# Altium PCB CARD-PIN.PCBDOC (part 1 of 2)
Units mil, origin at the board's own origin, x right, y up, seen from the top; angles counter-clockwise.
Board outline 5110 x 4320 mil, 2 copper layers (Top Layer, Bottom Layer); 210 components, 32 nets, 795 pads, 360 vias.
Unrouted connection lines stored in the file: 450.
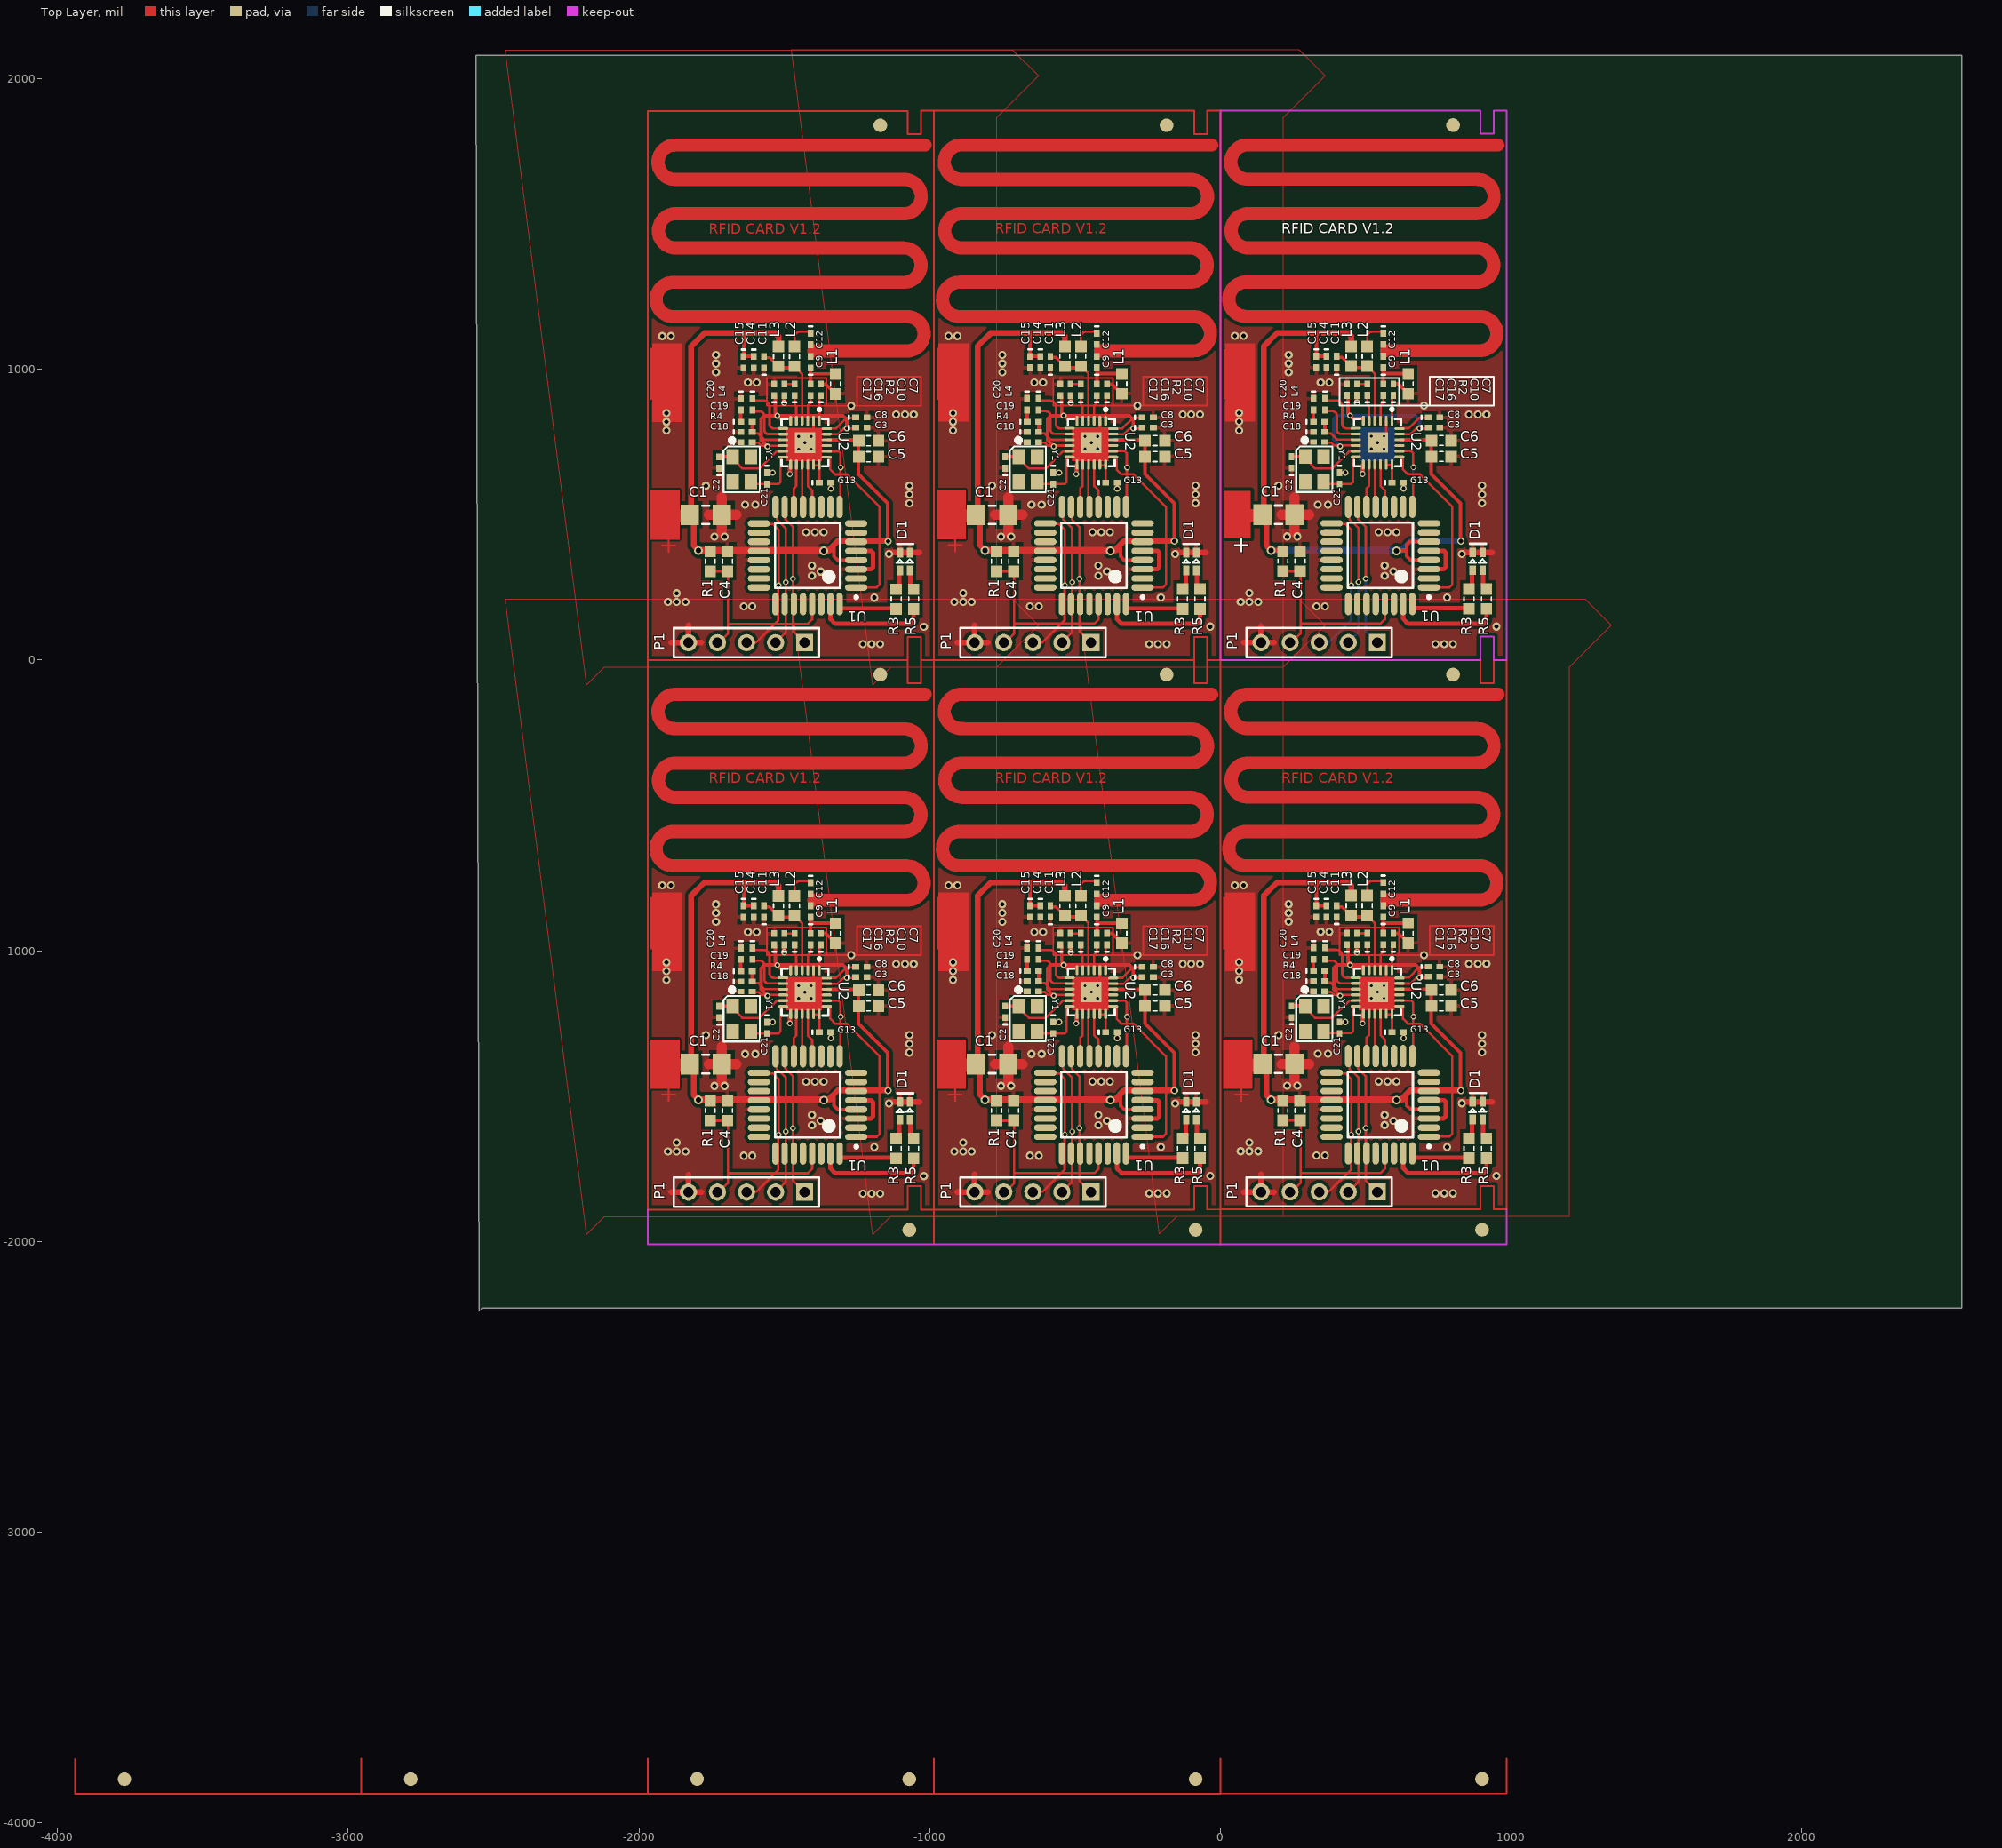
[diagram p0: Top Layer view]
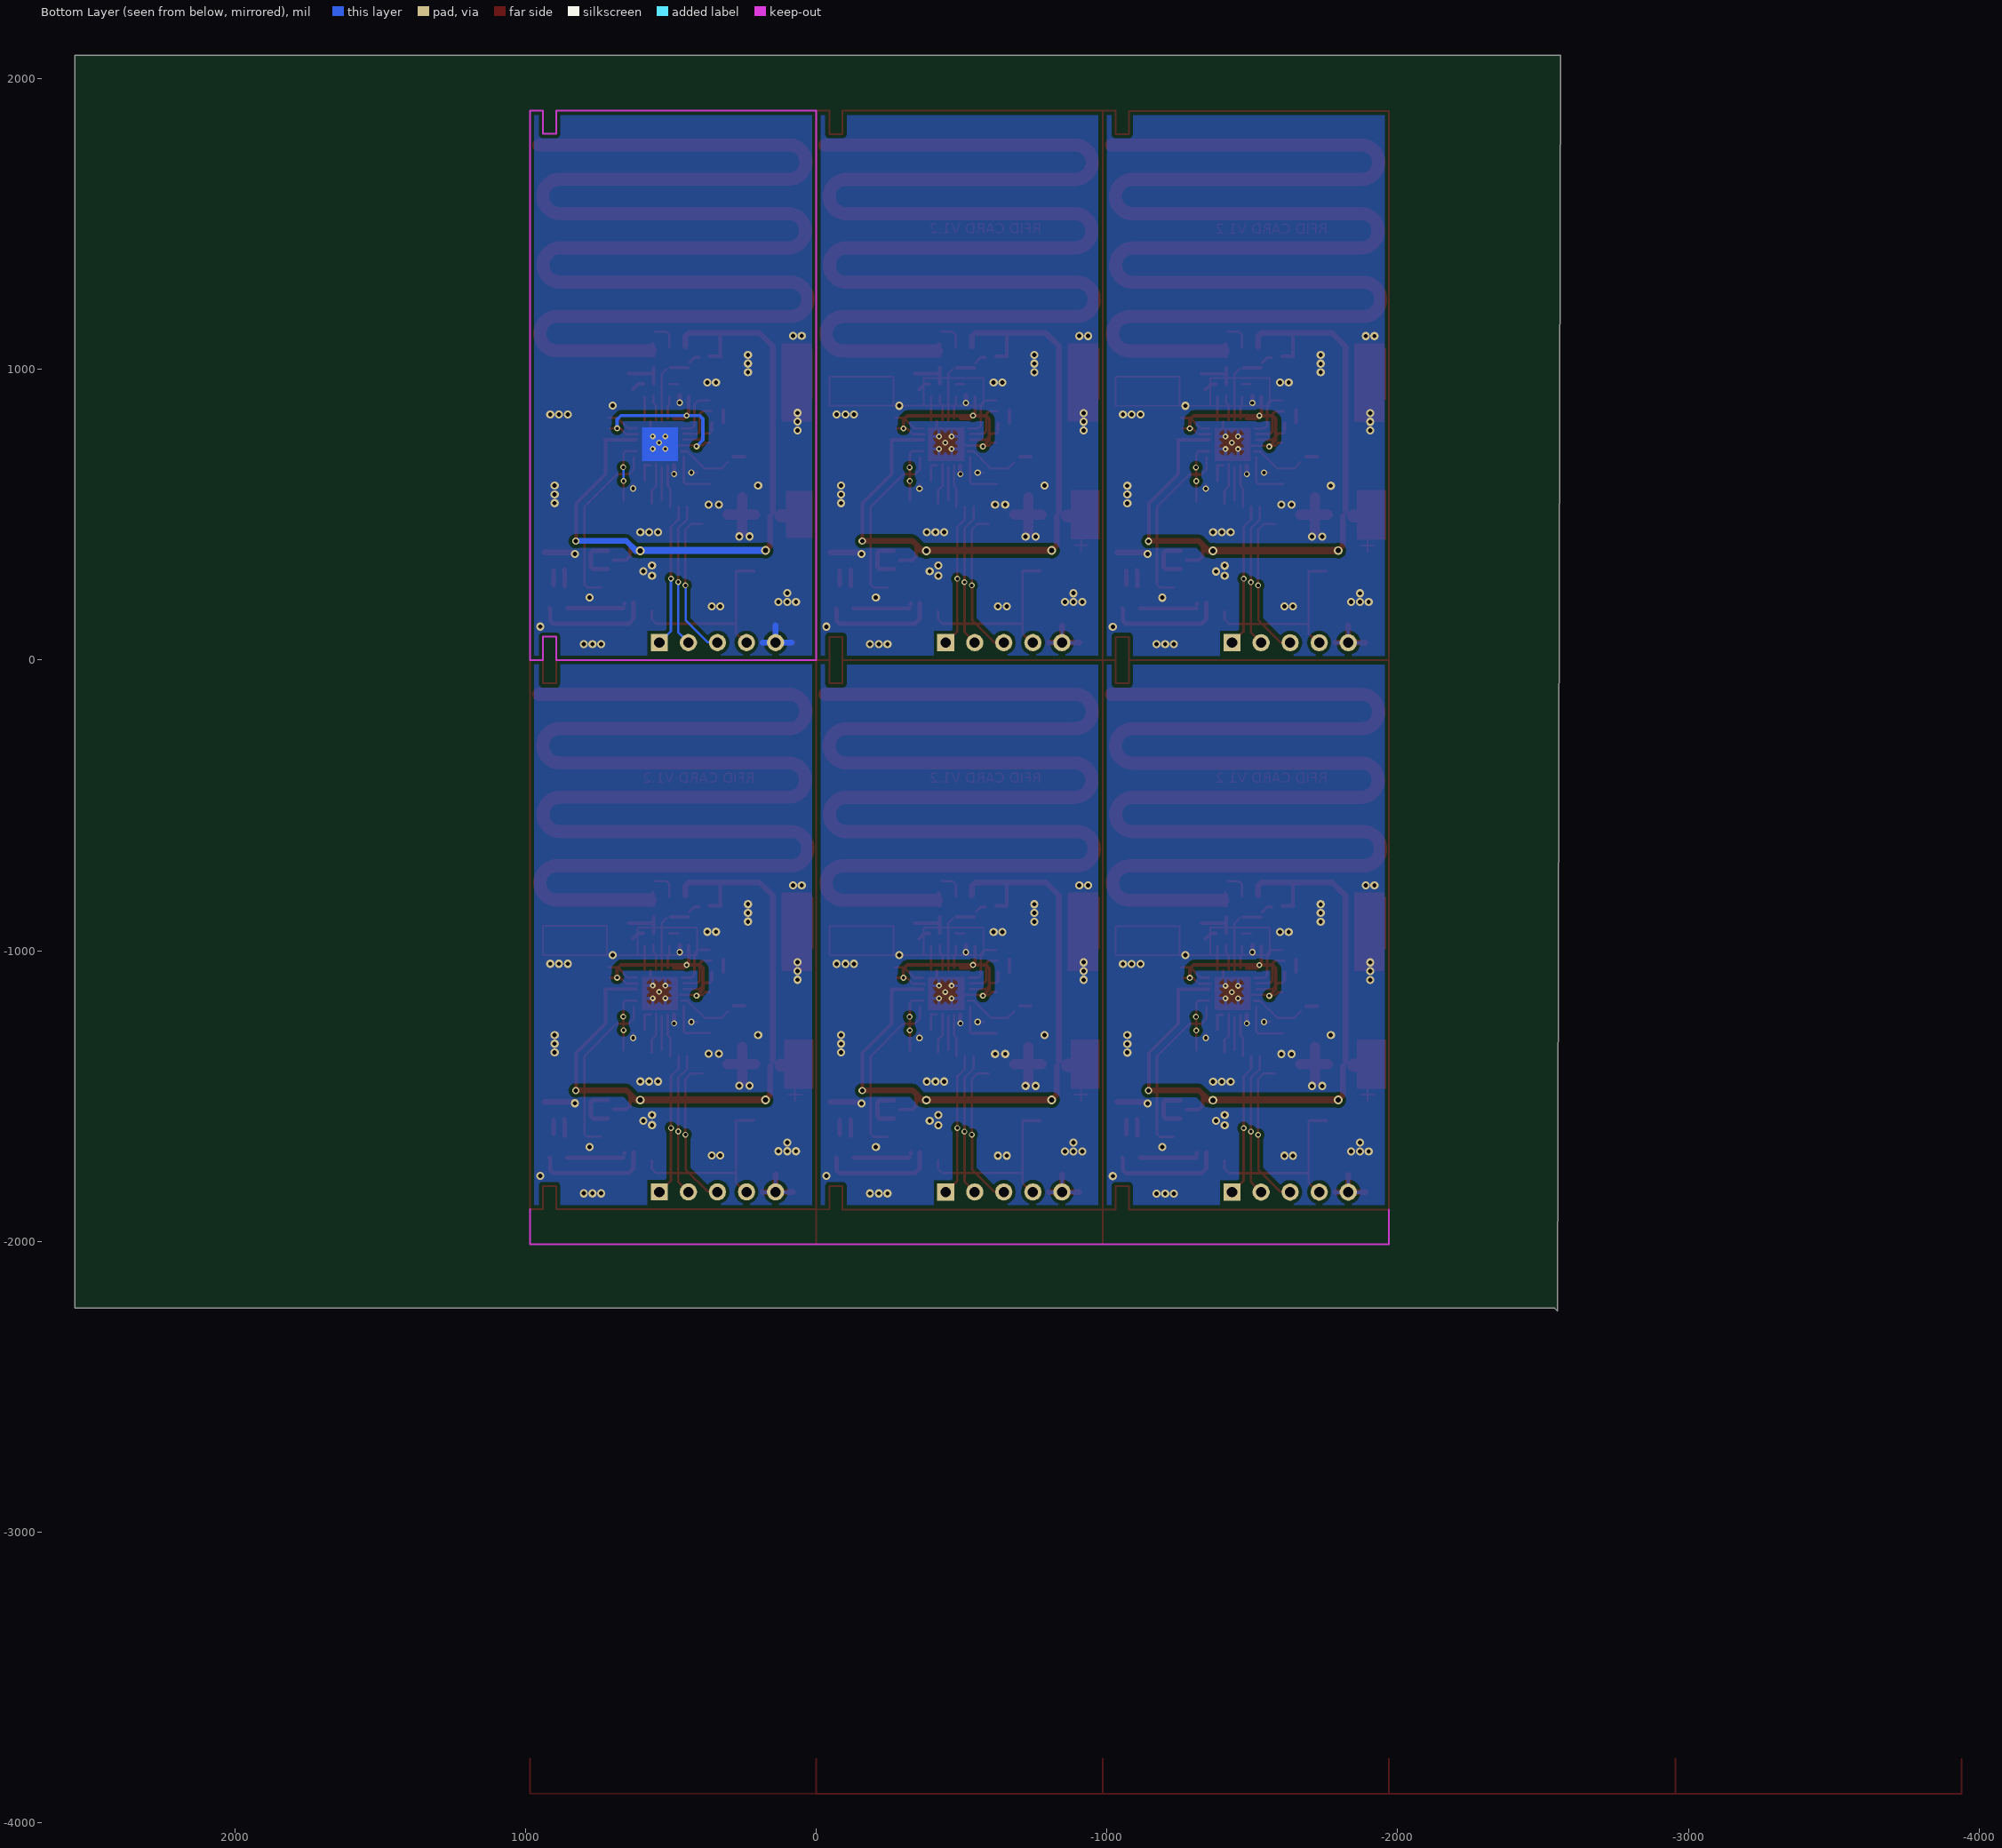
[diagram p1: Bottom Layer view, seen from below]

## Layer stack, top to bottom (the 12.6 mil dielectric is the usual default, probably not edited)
Top Layer: signal copper 1.4
Dielectric: core 12.6, FR-4, Dk 4.8
Bottom Layer: signal copper 1.4

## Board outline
-2560,2080 2550,2080 2550,-2230 -2540,-2230 -2550,-2240

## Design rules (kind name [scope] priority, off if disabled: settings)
Clearance [All] p1 off: gap=8
ComponentClearance [All] p1 off: gap=10 collisioncheckmode=3 verticalgap=10
DiffPairsRouting [All] p1 off: maxlimit=10 minlimit=10 mostfreqgap=10 maxuncoupledlength=500
HoleSize [All] p1: absolutevalues=TRUE maxlimit=100 minlimit=0 maxpercent=80.000 minpercent=20.000
PolygonConnect [All] p1: connectstyle=Relief reliefconductorwidth=12 reliefentries=4 polygonreliefangle="90 Angle"
RoutingVias [All] p1: holewidth=15 width=25 viastyle="Through Hole" minholewidth=8 minwidth=15 maxholewidth=80 maxwidth=50
SolderMaskExpansion [All] p1: expansion=4
TestPointUsage [All] p1: valid=0 allowmultiple=FALSE
Testpoint [All] p1: side=15 testpointundercomponent=TRUE minsize=40 maxsize=100 preferedsize=60 minholesize=0 maxholesize=40 preferedholesize=32 testpointgrid=1 style=1023 order=0-112345678
Width [All] p1: maxlimit=100 minlimit=8 preferedwidth=10 minimp=50.000000 maximp=50.000000 favimp=50.000000
16 further rules are at their usual default settings.

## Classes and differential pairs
component class card: C1 C2 C3 C4 C5 C6 C7 C8 C9 C10 C11 C12 C13 C14 C15 C16 C17 C18 C19 C20 C21 D1 D2 L1 L2 L3 L4 P1 P3 R1 R2 R3 R4 R5 U1 U2 Y1

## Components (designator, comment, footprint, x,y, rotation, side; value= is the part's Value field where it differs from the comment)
C1 "Cap" 3216[1206] 200,-1390 r180 top
C1 "Cap" 3216[1206] -785,-1390.24 r180 top
C1 "Cap" 3216[1206] -1770,-1390.47 r180 top
C1 "Cap" 3216[1206] -1770,499.53 r180 top
C1 "Cap" 3216[1206] -785,499.76 r180 top
C1 "Cap" 3216[1206] 200,500 r180 top
C2 "Cap" 0402-A 245,-1210 r90 top
C2 "Cap" 0402-A -740,-1210.24 r90 top
C2 "Cap" 0402-A -1725,-1210.47 r90 top
C2 "Cap" 0402-A -1725,679.53 r90 top
C2 "Cap" 0402-A -740,679.76 r90 top
C2 "Cap" 0402-A 245,680 r90 top
C3 "Cap" 0402-A 735,-1090 r0 top
C3 "Cap" 0402-A -250,-1090.24 r0 top
C3 "Cap" 0402-A -1235,-1090.47 r0 top
C3 "Cap" 0402-A -1235,799.53 r0 top
C3 "Cap" 0402-A -250,799.76 r0 top
C3 "Cap" 0402-A 735,800 r0 top
C4 "Cap" 0603 274,-1550 r90 top
C4 "Cap" 0603 -711,-1550.24 r90 top
C4 "Cap" 0603 -1696,-1550.47 r90 top
C4 "Cap" 0603 -1696,339.53 r90 top
C4 "Cap" 0603 -711,339.76 r90 top
C4 "Cap" 0603 274,340 r90 top
C5 "Cap" 0603 760,-1190 r0 top
C5 "Cap" 0603 -225,-1190.24 r0 top
C5 "Cap" 0603 -1210,-1190.47 r0 top
C5 "Cap" 0603 -1210,699.53 r0 top
C5 "Cap" 0603 -225,699.76 r0 top
C5 "Cap" 0603 760,700 r0 top
C6 "Cap" 0603 760,-1135 r0 top
C6 "Cap" 0603 -225,-1135.24 r0 top
C6 "Cap" 0603 -1210,-1135.47 r0 top
C6 "Cap" 0603 -1210,754.53 r0 top
C6 "Cap" 0603 -225,754.76 r0 top
C6 "Cap" 0603 760,755 r0 top
C7 "Cap" 0402-A 595,-960 r90 top
C7 "Cap" 0402-A -390,-960.24 r90 top
C7 "Cap" 0402-A -1375,-960.47 r90 top
C7 "Cap" 0402-A -1375,929.53 r90 top
C7 "Cap" 0402-A -390,929.76 r90 top
C7 "Cap" 0402-A 595,930 r90 top
C8 "Cap" 0402-A 735,-1055 r0 top
C8 "Cap" 0402-A -250,-1055.24 r0 top
C8 "Cap" 0402-A -1235,-1055.47 r0 top
C8 "Cap" 0402-A -1235,834.53 r0 top
C8 "Cap" 0402-A -250,834.76 r0 top
C8 "Cap" 0402-A 735,835 r0 top
C9 "Cap" 0402-A 560,-865 r90 top
C9 "Cap" 0402-A -425,-865.24 r90 top
C9 "Cap" 0402-A -1410,-865.47 r90 top
C9 "Cap" 0402-A -1410,1024.53 r90 top
C9 "Cap" 0402-A -425,1024.76 r90 top
C9 "Cap" 0402-A 560,1025 r90 top
C10 "Cap" 0402-A 560,-960 r90 top
C10 "Cap" 0402-A -425,-960.24 r90 top
C10 "Cap" 0402-A -1410,-960.47 r90 top
C10 "Cap" 0402-A -1410,929.53 r90 top
C10 "Cap" 0402-A -425,929.76 r90 top
C10 "Cap" 0402-A 560,930 r90 top
C11 "Cap" 0402-A 400,-865 r90 top
C11 "Cap" 0402-A -585,-865.24 r90 top
C11 "Cap" 0402-A -1570,-865.47 r90 top
C11 "Cap" 0402-A -1570,1024.53 r90 top
C11 "Cap" 0402-A -585,1024.76 r90 top
C11 "Cap" 0402-A 400,1025 r90 top
C12 "Cap" 0402-A 560,-785 r270 top
C12 "Cap" 0402-A -425,-785.24 r270 top
C12 "Cap" 0402-A -1410,-785.47 r270 top
C12 "Cap" 0402-A -1410,1104.53 r270 top
C12 "Cap" 0402-A -425,1104.76 r270 top
C12 "Cap" 0402-A 560,1105 r270 top
C13 "Cap" 0402-A 610,-1280 r0 top
C13 "Cap" 0402-A -375,-1280.24 r0 top
C13 "Cap" 0402-A -1360,-1280.47 r0 top
C13 "Cap" 0402-A -1360,609.53 r0 top
C13 "Cap" 0402-A -375,609.76 r0 top
C13 "Cap" 0402-A 610,610 r0 top
C14 "Cap" 0402-A 365,-865 r270 top
C14 "Cap" 0402-A -620,-865.24 r270 top
C14 "Cap" 0402-A -1605,-865.47 r270 top
C14 "Cap" 0402-A -1605,1024.53 r270 top
C14 "Cap" 0402-A -620,1024.76 r270 top
C14 "Cap" 0402-A 365,1025 r270 top
C15 "Cap" 0402-A 330,-865 r270 top
C15 "Cap" 0402-A -655,-865.24 r270 top
C15 "Cap" 0402-A -1640,-865.47 r270 top
C15 "Cap" 0402-A -1640,1024.53 r270 top
C15 "Cap" 0402-A -655,1024.76 r270 top
C15 "Cap" 0402-A 330,1025 r270 top
C16 "Cap" 0402-A 470,-960 r90 top
C16 "Cap" 0402-A -515,-960.24 r90 top
C16 "Cap" 0402-A -1500,-960.47 r90 top
C16 "Cap" 0402-A -1500,929.53 r90 top
C16 "Cap" 0402-A -515,929.76 r90 top
C16 "Cap" 0402-A 470,930 r90 top
C17 "Cap" 0402-A 435,-960 r90 top
C17 "Cap" 0402-A -550,-960.24 r90 top
C17 "Cap" 0402-A -1535,-960.47 r90 top
C17 "Cap" 0402-A -1535,929.53 r90 top
C17 "Cap" 0402-A -550,929.76 r90 top
C17 "Cap" 0402-A 435,930 r90 top
C18 "Cap" 0402-A 340,-1140 r0 top
C18 "Cap" 0402-A -645,-1140.24 r0 top
C18 "Cap" 0402-A -1630,-1140.47 r0 top
C18 "Cap" 0402-A -1630,749.53 r0 top
C18 "Cap" 0402-A -645,749.76 r0 top
C18 "Cap" 0402-A 340,750 r0 top
C19 "Cap" 0402-A 340,-1105 r0 top
C19 "Cap" 0402-A -645,-1105.24 r0 top
C19 "Cap" 0402-A -1630,-1105.47 r0 top
C19 "Cap" 0402-A -1630,784.53 r0 top
C19 "Cap" 0402-A -645,784.76 r0 top
C19 "Cap" 0402-A 340,785 r0 top
C20 "Cap" 0402-A 320,-1010 r270 top
C20 "Cap" 0402-A -665,-1010.24 r270 top
C20 "Cap" 0402-A -1650,-1010.47 r270 top
C20 "Cap" 0402-A -1650,879.53 r270 top
C20 "Cap" 0402-A -665,879.76 r270 top
C20 "Cap" 0402-A 320,880 r270 top
C21 "Cap" 0402-A 410,-1265 r270 top
C21 "Cap" 0402-A -575,-1265.24 r270 top
C21 "Cap" 0402-A -1560,-1265.47 r270 top
C21 "Cap" 0402-A -1560,624.53 r270 top
C21 "Cap" 0402-A -575,624.76 r270 top
C21 "Cap" 0402-A 410,625 r270 top
D1 "LED" 0603-LED-DOUBLE 902,-1580 r90 top
D1 "LED" 0603-LED-DOUBLE -83,-1580.24 r90 top
D1 "LED" 0603-LED-DOUBLE -1068,-1580.47 r90 top
D1 "LED" 0603-LED-DOUBLE -1068,309.53 r90 top
D1 "LED" 0603-LED-DOUBLE -83,309.76 r90 top
D1 "LED" 0603-LED-DOUBLE 902,310 r90 top
L1 "Inductor" 0603 646,-940 r270 top
L1 "Inductor" 0603 -339,-940.24 r270 top
L1 "Inductor" 0603 -1324,-940.47 r270 top
L1 "Inductor" 0603 -1324,949.53 r270 top
L1 "Inductor" 0603 -339,949.76 r270 top
L1 "Inductor" 0603 646,950 r270 top
L2 "Inductor" 0603 505,-845 r90 top
L2 "Inductor" 0603 -480,-845.24 r90 top
L2 "Inductor" 0603 -1465,-845.47 r90 top
L2 "Inductor" 0603 -1465,1044.53 r90 top
L2 "Inductor" 0603 -480,1044.76 r90 top
L2 "Inductor" 0603 505,1045 r90 top
L3 "Inductor" 0603 450,-845 r90 top
L3 "Inductor" 0603 -535,-845.24 r90 top
L3 "Inductor" 0603 -1520,-845.47 r90 top
L3 "Inductor" 0603 -1520,1044.53 r90 top
L3 "Inductor" 0603 -535,1044.76 r90 top
L3 "Inductor" 0603 450,1045 r90 top
L4 "Inductor" 0402-A 360,-1010 r270 top
L4 "Inductor" 0402-A -625,-1010.24 r270 top
L4 "Inductor" 0402-A -1610,-1010.47 r270 top
L4 "Inductor" 0402-A -1610,879.53 r270 top
L4 "Inductor" 0402-A -625,879.76 r270 top
L4 "Inductor" 0402-A 360,880 r270 top
P1 "ISP" HDR1X5 540,-1830 r180 top
P1 "ISP" HDR1X5 -445,-1830.24 r180 top
P1 "ISP" HDR1X5 -1430,-1830.47 r180 top
P1 "ISP" HDR1X5 -1430,59.53 r180 top
P1 "ISP" HDR1X5 -445,59.76 r180 top
P1 "ISP" HDR1X5 540,60 r180 top
R1 "Res1" 0603 215,-1550 r90 top
R1 "Res1" 0603 -770,-1550.24 r90 top
R1 "Res1" 0603 -1755,-1550.47 r90 top
R1 "Res1" 0603 -1755,339.53 r90 top
R1 "Res1" 0603 -770,339.76 r90 top
R1 "Res1" 0603 215,340 r90 top
R2 "Res1" 0402-A 505,-960 r90 top
R2 "Res1" 0402-A -480,-960.24 r90 top
R2 "Res1" 0402-A -1465,-960.47 r90 top
R2 "Res1" 0402-A -1465,929.53 r90 top
R2 "Res1" 0402-A -480,929.76 r90 top
R2 "Res1" 0402-A 505,930 r90 top
R3 "Res1" 0603 855,-1680 r90 top
R3 "Res1" 0603 -130,-1680.24 r90 top
R3 "Res1" 0603 -1115,-1680.47 r90 top
R3 "Res1" 0603 -1115,209.53 r90 top
R3 "Res1" 0603 -130,209.76 r90 top
R3 "Res1" 0603 855,210 r90 top
R4 "Res1" 0402-A 340,-1070 r0 top
R4 "Res1" 0402-A -645,-1070.24 r0 top
R4 "Res1" 0402-A -1630,-1070.47 r0 top
R4 "Res1" 0402-A -1630,819.53 r0 top
R4 "Res1" 0402-A -645,819.76 r0 top
R4 "Res1" 0402-A 340,820 r0 top
R5 "Res1" 0603 915,-1680 r90 top
R5 "Res1" 0603 -70,-1680.24 r90 top
R5 "Res1" 0603 -1055,-1680.47 r90 top
R5 "Res1" 0603 -1055,209.53 r90 top
R5 "Res1" 0603 -70,209.76 r90 top
R5 "Res1" 0603 915,210 r90 top
U1 "ATmega8-16AC" 32A_M 550,-1530 r180 top
U1 "ATmega8-16AC" 32A_M -435,-1530.24 r180 top
U1 "ATmega8-16AC" 32A_M -1420,-1530.47 r180 top
U1 "ATmega8-16AC" 32A_M -1420,359.53 r180 top
U1 "ATmega8-16AC" 32A_M -435,359.76 r180 top
U1 "ATmega8-16AC" 32A_M 550,360 r180 top
U2 "A7139" QFN24N 541,-1142 r270 top
U2 "A7139" QFN24N -444,-1142.24 r270 top
U2 "A7139" QFN24N -1429,-1142.47 r270 top
U2 "A7139" QFN24N -1429,747.53 r270 top
U2 "A7139" QFN24N -444,747.76 r270 top
U2 "A7139" QFN24N 541,748 r270 top
Y1 "12.8M CL=20pF" XT3225 355,-1190 r270 top
Y1 "12.8M CL=20pF" XT3225 -630,-1190.24 r270 top
Y1 "12.8M CL=20pF" XT3225 -1615,-1190.47 r270 top
Y1 "12.8M CL=20pF" XT3225 -1615,699.53 r270 top
Y1 "12.8M CL=20pF" XT3225 -630,699.76 r270 top
Y1 "12.8M CL=20pF" XT3225 355,700 r270 top

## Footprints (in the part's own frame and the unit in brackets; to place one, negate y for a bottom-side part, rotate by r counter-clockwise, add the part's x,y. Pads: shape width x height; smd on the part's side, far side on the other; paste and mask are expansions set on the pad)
32A_M [mm] "32-Pin Thin Quad Flat Pack 0.8 mm Pitch, IPC Low Density"
  oval 1.95x0.559 smd: 1(-4.25,2.8) 2(-4.25,2) 3(-4.25,1.2) 4(-4.25,0.4) 5(-4.25,-0.4) 6(-4.25,-1.2) 7(-4.25,-2) 8(-4.25,-2.8) 17(4.25,-2.8) 18(4.25,-2) 19(4.25,-1.2) 20(4.25,-0.4) 21(4.25,0.4) 22(4.25,1.2) 23(4.25,2) 24(4.25,2.8)
  oval 0.559x1.95 smd: 9(-2.8,-4.25) 10(-2,-4.25) 11(-1.2,-4.25) 12(-0.4,-4.25) 13(0.4,-4.25) 14(1.2,-4.25) 15(2,-4.25) 16(2.8,-4.25) 25(2.8,4.25) 26(2,4.25) 27(1.2,4.25) 28(0.4,4.25) 29(-0.4,4.25) 30(-1.2,4.25) 31(-2,4.25) 32(-2.8,4.25)
  silkscreen extent -4.38,-2.85 2.85,3.77, body extent -3.5,-3.5 3.5,3.5, height 1.2
0402-A [mm] "Chip Inductor; Body 1 x 0.5 mm (LxW typ)"
  rect 0.6x0.5 smd: 1(-0.5,0) 2(0.5,0)
  silkscreen extent -1.1,-0.15 -1.1,0.15
0603 [mm]
  rect 1x1 smd: 1(-0.864,0) 2(0.864,0)
  silkscreen extent -0.18,-0.43 0.18,0.43
0603-LED-DOUBLE [mil]
  rect 33x22 smd: 1(-1,34) 2(-1,0) 3(60,34) 4(60,0)
  silkscreen extent 24,-12 90,47
3216[1206] [mm] "Chip Resistor; Body 3.2 x 1.6 mm (LxW typ)"
  rect 1.6x1.8 smd: 1(-1.4,0) 2(1.4,0)
  silkscreen extent -0.3,-0.8 0.3,0.8
HDR1X5 [mm] "Connector; Header; 5 Position"
  rect 1.5x1.5 hole 0.9: 1(0,0)
  round 1.5 hole 0.9: 2(2.54,0) 3(5.08,0) 4(7.62,0) 5(10.16,0)
  silkscreen extent -1.27,-1.27 11.43,1.27
QFN24N [mm] "QFN, 24-Leads, Body 4.1x4.1mm (max), Pitch 0.50mm, IPC Medium Density"
  oval 0.889x0.25 smd: 1(-1.905,1.25) 2(-1.905,0.75) 3(-1.905,0.25) 4(-1.905,-0.25) 5(-1.905,-0.75) 6(-1.905,-1.25) 13(1.905,-1.25) 14(1.905,-0.75) 15(1.905,-0.25) 16(1.905,0.25) 17(1.905,0.75) 18(1.905,1.25)
  oval 0.25x0.889 smd: 7(-1.25,-1.905) 8(-0.75,-1.905) 9(-0.25,-1.905) 10(0.25,-1.905) 11(0.75,-1.905) 12(1.25,-1.905) 19(1.25,1.905) 20(0.75,1.905) 21(0.25,1.905) 22(-0.25,1.905) 23(-0.75,1.905) 24(-1.219,1.905)
  rect 1.8x1.8 smd: 25(0,0)
  silkscreen extent -3.02,-2.05 2.05,2.05, body extent -2.05,-2.05 2.05,2.05, height 0.8
XT3225 [mm]
  rect 1.3x1.1 smd: 1(0,-1.6) 2(2.2,-1.6) 3(2.2,0) 4(0,0)
  silkscreen extent -1.6,-2.39 3.1,0.76

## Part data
C1 C1 C1 C1 C1 C1 C2 C2 C2 C2 C2 C2 C3 C3 C3 C3 C3 C3 C4 C4 C4 C4 C4 C4 C5 C5 C5 C5 C5 C5 C6 C6 C6 C6 C6 C6 C7 C7 C7 C7 C7 C7 C8 C8 C8 C8 C8 C8 C9 C9 C9 C9 C9 C9 C10 C10 C10 C10 C10 C10 C11 C11 C11 C11 C11 C11 C12 C12 C12 C12 C12 C12 C13 C13 C13 C13 C13 C13 C14 C14 C14 C14 C14 C14 C15 C15 C15 C15 C15 C15 C16 C16 C16 C16 C16 C16 C17 C17 C17 C17 C17 C17 C18 C18 C18 C18 C18 C18 C19 C19 C19 C19 C19 C19 C20 C20 C20 C20 C20 C20 C21 C21 C21 C21 C21 C21: "Capacitor"
D1 D1 D1 D1 D1 D1: library part LED-DOUBLE
P1 P1 P1 P1 P1 P1: library part "Header 5", "Header, 5-Pin"
R1 R1 R1 R1 R1 R1 R2 R2 R2 R2 R2 R2 R3 R3 R3 R3 R3 R3 R4 R4 R4 R4 R4 R4 R5 R5 R5 R5 R5 R5: "Resistor"
U1 U1 U1 U1 U1 U1: "8-Bit AVR Microcontroller with 8K Bytes of In-System Programmable Flash Memory"
Y1 Y1 Y1 Y1 Y1 Y1: library part XTAL, "Crystal Oscillator"

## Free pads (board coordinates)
  round 47.24 smd: 3(-1170,-50.47) 3(-1170,1839.53) 3(-185,-50.24) 3(-185,1839.76) 3(800,-50) 3(800,1840) 6(-1070,-3850.47) 6(-1070,-1960.47) 6(-85,-3850.24) 6(-85,-1960.24) 6(900,-3850) 6(900,-1960) 7(-3770,-3850.47) 7(-2785,-3850.24) 7(-1800,-3850)

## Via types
v1: diameter 28, hole 15, Top Layer to Bottom Layer, 240 vias
v2: diameter 20, hole 12, Top Layer to Bottom Layer, 36 vias
v3: diameter 20, hole 10, Top Layer to Bottom Layer, tented top, 30 vias
v4: diameter 22, hole 13, Top Layer to Bottom Layer, 18 vias
v5: diameter 21, hole 11, Top Layer to Bottom Layer, 18 vias
v6: diameter 30, hole 18, Top Layer to Bottom Layer, 12 vias
v7: diameter 25, hole 15, Top Layer to Bottom Layer, 6 vias

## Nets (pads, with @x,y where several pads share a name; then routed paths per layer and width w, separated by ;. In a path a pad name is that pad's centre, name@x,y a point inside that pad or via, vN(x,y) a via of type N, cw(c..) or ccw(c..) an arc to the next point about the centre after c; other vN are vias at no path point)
GIO1: U1.1 U2.19 | length 3555.5
  Top Layer w8: U2.19@-1342,-1193.47 -1342,-1234.47 -1325,-1251.47 -1284,-1251.47 -1172,-1363.47 -1172,-1630.47 -1182,-1640.47 U1.1@-1229,-1640.47 ; U2.19@-1342,696.53 -1342,655.53 -1325,638.53 -1284,638.53 -1172,526.53 -1172,259.53 -1182,249.53 U1.1@-1229,249.53 ; U2.19@-357,-1193.24 -357,-1234.24 -340,-1251.24 -299,-1251.24 -187,-1363.24 -187,-1630.24 -197,-1640.24 U1.1@-244,-1640.24 ; U2.19@-357,696.76 -357,655.76 -340,638.76 -299,638.76 -187,526.76 -187,259.76 -197,249.76 U1.1@-244,249.76 ; U2.19@628,-1193 628,-1234 645,-1251 686,-1251 798,-1363 798,-1630 788,-1640 U1.1@741,-1640 ; U2.19@628,697 628,656 645,639 686,639 798,527 798,260 788,250 U1.1@741,250
GIO2: U1.9 U2.20 | length 1283.3
  Top Layer w8: U2.20@-1351.44,-1172 -1313.47,-1172 -1307,-1178.47 v2@-1307,-1228.47 ; U2.20@-1351.44,718 -1313.47,718 -1307,711.53 v2@-1307,661.53 ; U1.9@-1307,-1343.24 v2(-1307,-1274.47) ; v2@-1307,-1271.47 v2@-1307,-1223.47 ; U1.9@-1307,546.76 v2(-1307,615.53) ; v2@-1307,618.53 v2@-1307,666.53 ; U2.20@-366.44,-1171.76 -328.47,-1171.76 -322,-1178.24 v2@-322,-1228.24 ; U2.20@-366.44,718.24 -328.47,718.24 -322,711.76 v2@-322,661.76 ; U1.9@-322,-1343 v2(-322,-1274.24) ; v2@-322,-1271.24 v2@-322,-1223.24 ; U1.9@-322,547 v2(-322,615.76) ; v2@-322,618.76 v2@-322,666.76 ; U2.20@618.56,-1171.53 656.53,-1171.53 663,-1178 v2@663,-1228 ; U2.20@618.56,718.47 656.53,718.47 663,712 v2@663,662 ; U1.9@663,-1342.76 v2(663,-1274) ; v2@663,-1271 v2@663,-1223 ; U1.9@663,547.24 v2(663,616)
  Bottom Layer w8: v2@663,619 v2@663,667
  other v2: -1306,-1227.47 -321,-1227.24 664,-1227 -1306,662.53 -321,662.76 664,663
GND: C1.1 C2.1 C3.2 C4.2 C5.2 C6.2 C7.2 C8.2 C11.1 C13.2 C14.2 C15.2 C16.1 C17.2 C18.1 C19.1 C20.1 C21.1 D1.3 D1.4 L1.2 P1.5 U1.3 U1.5 U1.21 U2.2 U2.13 U2.25 | length 5774.5
  Top Layer w10: v4@-1550,-1245.47 v4@-1541,-1245.47 ; v4@-1550,644.53 v4@-1541,644.53 ; U2.25@-1399.47,-1112.94 U2.2@-1399.47,-1069.47 ; U2.25@-1399.47,777.06 U2.2@-1399.47,820.53 ; v4@-1340,-1299.61 C13.2@-1340,-1285.47 ; v4@-1340,590.39 C13.2@-1340,604.53 ; v4@-565,-1245.24 v4@-556,-1245.24 ; v4@-565,644.76 v4@-556,644.76 ; U2.25@-414.47,-1112.71 U2.2@-414.47,-1069.24 ; U2.25@-414.47,777.29 U2.2@-414.47,820.76 ; v4@-355,-1299.38 C13.2@-355,-1285.24 ; v4@-355,590.62 C13.2@-355,604.76 ; v4@420,-1245 v4@429,-1245 ; v4@420,645 v4@429,645 ; U2.25@570.53,-1112.47 U2.2@570.53,-1069 ; U2.25@570.53,777.53 U2.2@570.53,821 ; v4@630,-1299.14 C13.2@630,-1285 ; v4@630,590.86 C13.2@630,605
  Top Layer w12: C7.2@-1375,-940.79 -1357.69,-940.79 L1.2@-1339,-959.47 ; C7.2@-1375,949.21 -1357.69,949.21 L1.2@-1339,930.53 ; C7.2@-390,-940.55 -372.69,-940.55 L1.2@-354,-959.24 ; C7.2@-390,949.45 -372.69,949.45 L1.2@-354,930.76 ; C7.2@595,-940.31 612.31,-940.31 L1.2@631,-959 ; C7.2@595,949.69 612.31,949.69 L1.2@631,931
  Top Layer w15: v4@-1500,-1006.47 C16.1@-1500,-980.16 ; v4@-1500,883.53 C16.1@-1500,909.84 ; v2@-1480,-1250.47 U2.13@-1480,-1220.47 ; v2@-1480,639.53 U2.13@-1480,669.53 ; U1.3@-1252.68,-1577.72 -1202.24,-1577.72 -1195,-1570.47 -1195,-1520.47 -1200.75,-1514.72 U1.5@-1252.68,-1514.72 ; U1.3@-1252.68,312.28 -1202.24,312.28 -1195,319.53 -1195,369.53 -1200.75,375.28 U1.5@-1252.68,375.28 ; v4@-515,-1006.24 C16.1@-515,-979.92 ; v4@-515,883.76 C16.1@-515,910.08 ; v2@-495,-1250.24 U2.13@-495,-1220.24 ; v2@-495,639.76 U2.13@-495,669.76 ; U1.3@-267.68,-1577.48 -217.24,-1577.48 -210,-1570.24 -210,-1520.24 -215.75,-1514.49 U1.5@-267.68,-1514.49 ; U1.3@-267.68,312.52 -217.24,312.52 -210,319.76 -210,369.76 -215.75,375.51 U1.5@-267.68,375.51 ; v4@470,-1006 C16.1@470,-979.68 ; v4@470,884 C16.1@470,910.32 ; v2@490,-1250 U2.13@490,-1220 ; v2@490,640 U2.13@490,670 ; U1.3@717.32,-1577.24 767.76,-1577.24 775,-1570 775,-1520 769.25,-1514.25 U1.5@717.32,-1514.25 ; U1.3@717.32,312.76 767.76,312.76 775,320 775,370 769.25,375.75 U1.5@717.32,375.75
  Top Layer w20: -1890,-1830.47 -1785,-1830.47 -1885,-1830.47 ; -1890,59.53 -1785,59.53 -1885,59.53 ; P1.5@-1830,-1830.47 -1830,-1775.47 ; P1.5@-1830,-1825.47 -1830,-1770.47 ; P1.5@-1830,59.53 -1830,114.53 ; P1.5@-1830,64.53 -1830,119.53 ; v1@-1130,-1520.47 -1035,-1520.47 ; v1@-1130,369.53 -1035,369.53 ; -905,-1830.24 -800,-1830.24 -900,-1830.24 ; -905,59.76 -800,59.76 -900,59.76 ; P1.5@-845,-1830.24 -845,-1775.24 ; P1.5@-845,-1825.24 -845,-1770.24 ; P1.5@-845,59.76 -845,114.76 ; P1.5@-845,64.76 -845,119.76 ; v1@-145,-1520.24 -50,-1520.24 ; v1@-145,369.76 -50,369.76 ; 80,-1830 185,-1830 85,-1830 ; 80,60 185,60 ; P1.5@140,-1830 140,-1775 ; P1.5@140,-1825 140,-1770 ; P1.5@140,60 140,115 ; v1@840,-1520 935,-1520 ; v1@840,370 935,370
  Top Layer w35: -1760,-1390.47 -1665,-1390.47 ; -1760,499.53 -1665,499.53 ; -1715,-1450.47 -1715,-1330.47 ; -1715,439.53 -1715,559.53 ; -775,-1390.24 -680,-1390.24 ; -775,499.76 -680,499.76 ; -730,-1450.24 -730,-1330.24 ; -730,439.76 -730,559.76 ; 210,-1390 305,-1390 ; 210,500 305,500 ; 255,-1450 255,-1330 ; 255,440 255,560
  Bottom Layer w20: 85,60 185,60 ; P1.5@140,65 140,120
  other v1: -1230,-1835.47 -1200,-1835.47 -1170,-1835.47 -245,-1835.24 -215,-1835.24 -185,-1835.24 740,-1835 770,-1835 800,-1835 -1020,-1775.47 -35,-1775.24 950,-1775 -1640,-1705.47 -1610,-1705.47 -655,-1705.24 -625,-1705.24 330,-1705 360,-1705 -1900,-1690.47 -1870,-1690.47 -1840,-1690.47 -915,-1690.24 -885,-1690.24 -855,-1690.24 70,-1690 100,-1690 130,-1690 -1190,-1675.47 -205,-1675.24 780,-1675 -1870,-1660.47 -885,-1660.24 100,-1660 -1405,-1600.47 -420,-1600.24 565,-1600 -1375,-1585.47 -390,-1585.24 595,-1585 -1405,-1565.47 -420,-1565.24 565,-1565 -1140,-1525.47 -155,-1525.24 830,-1525 -1740,-1465.47 -1705,-1465.47 -755,-1465.24 -720,-1465.24 230,-1465 265,-1465 -1425,-1450.47 -1395,-1450.47 -1365,-1450.47 -440,-1450.24 -410,-1450.24 -380,-1450.24 545,-1450 575,-1450 605,-1450 -1635,-1355.47 -1600,-1355.47 -650,-1355.24 -615,-1355.24 335,-1355 370,-1355 -1070,-1350.47 -85,-1350.24 900,-1350 -1070,-1320.47 -85,-1320.24 900,-1320 -1770,-1290.47 -1070,-1290.47 -785,-1290.24 -85,-1290.24 200,-1290 900,-1290 -1905,-1100.47 -920,-1100.24 65,-1100 -1905,-1070.47 -920,-1070.24 65,-1070 -1115,-1045.47 -1085,-1045.47 -1055,-1045.47 -130,-1045.24 -100,-1045.24 -70,-1045.24 855,-1045 885,-1045 915,-1045 -1905,-1040.47 -920,-1040.24 65,-1040 -1270,-1015.47 -285,-1015.24 700,-1015 -1625,-935.47 -1595,-935.47 -640,-935.24 -610,-935.24 345,-935 375,-935 -1735,-900.47 -750,-900.24 235,-900 -1735,-870.47 -750,-870.24 235,-870 -1735,-840.47 -750,-840.24 235,-840 -1920,-775.47 -1890,-775.47 -935,-775.24 -905,-775.24 50,-775 80,-775 -1230,54.53 -1200,54.53 -1170,54.53 -245,54.76 -215,54.76 -185,54.76 740,55 770,55 800,55 -1020,114.53 -35,114.76 950,115 -1640,184.53 -1610,184.53 -655,184.76 -625,184.76 330,185 360,185 -1900,199.53 -1870,199.53 -1840,199.53 -915,199.76 -885,199.76 -855,199.76 70,200 100,200 130,200 -1190,214.53 -205,214.76 780,215 -1870,229.53 -885,229.76 100,230 -1405,289.53 -420,289.76 565,290 -1375,304.53 -390,304.76 595,305 -1405,324.53 -420,324.76 565,325 -1140,364.53 -155,364.76 830,365 -1740,424.53 -1705,424.53 -755,424.76 -720,424.76 230,425 265,425 -1425,439.53 -1395,439.53 -1365,439.53 -440,439.76 -410,439.76 -380,439.76 545,440 575,440 605,440 -1635,534.53 -1600,534.53 -650,534.76 -615,534.76 335,535 370,535 -1070,539.53 -85,539.76 900,540 -1070,569.53 -85,569.76 900,570 -1770,599.53 -1070,599.53 -785,599.76 -85,599.76 200,600 900,600 -1905,789.53 -920,789.76 65,790 -1905,819.53 -920,819.76 65,820 -1115,844.53 -1085,844.53 -1055,844.53 -130,844.76 -100,844.76 -70,844.76 855,845 885,845 915,845 -1905,849.53 -920,849.76 65,850 -1270,874.53 -285,874.76 700,875 -1625,954.53 -1595,954.53 -640,954.76 -610,954.76 345,955 375,955 -1735,989.53 -750,989.76 235,990 -1735,1019.53 -750,1019.76 235,1020 -1735,1049.53 -750,1049.76 235,1050 -1920,1114.53 -1890,1114.53 -935,1114.76 -905,1114.76 50,1115 80,1115
  other v2: -1481,-1250.47 -496,-1250.24 489,-1250 -1481,639.53 -496,639.76 489,640
  other v3: -1450.65,-1164.13 -1407.35,-1164.13 -465.65,-1163.89 -422.35,-1163.89 519.35,-1163.65 562.65,-1163.65 -1429,-1142.47 -444,-1142.24 541,-1142 -1450.65,-1120.82 -1407.35,-1120.82 -465.65,-1120.58 -422.35,-1120.58 519.35,-1120.35 562.65,-1120.35 -1450.65,725.87 -1407.35,725.87 -465.65,726.11 -422.35,726.11 519.35,726.35 562.65,726.35 -1429,747.53 -444,747.76 541,748 -1450.65,769.18 -1407.35,769.18 -465.65,769.42 -422.35,769.42 519.35,769.65 562.65,769.65
  other v4: -1340,-1300.47 -355,-1300.24 630,-1300 -1540,-1245.47 -555,-1245.24 430,-1245 -1500,-1005.47 -515,-1005.24 470,-1005 -1340,589.53 -355,589.76 630,590 -1540,644.53 -555,644.76 430,645 -1500,884.53 -515,884.76 470,885
MISO: P1.2 U1.16 | length 2984
  Top Layer w8: P1.2@-1530,-1835.47 -1530,-1829.47 -1495,-1794.47 v2(-1495,-1622.47) ; P1.2@-1530,54.53 -1530,60.53 -1495,95.53 v2(-1495,267.53) ; U1.16@-1526,-1363.47 -1526,-1406.47 -1495,-1437.47 v2@-1495,-1620.47 ; U1.16@-1526,526.53 -1526,483.53 -1495,452.53 v2@-1495,269.53 ; P1.2@-545,-1835.24 -545,-1829.24 -510,-1794.24 v2(-510,-1622.24) ; P1.2@-545,54.76 -545,60.76 -510,95.76 v2(-510,267.76) ; U1.16@-541,-1363.24 -541,-1406.24 -510,-1437.24 v2@-510,-1620.24 ; U1.16@-541,526.76 -541,483.76 -510,452.76 v2@-510,269.76 ; P1.2@440,-1835 440,-1829 475,-1794 v2(475,-1622) ; U1.16@444,-1363 444,-1406 475,-1437 v2@475,-1620 ; U1.16@444,527 444,484 475,453 v2@475,270
  Bottom Layer w8: P1.2@440,55 440,61 475,96 v2(475,268)
MOSI: P1.1 U1.15 | length 2976.6
  Top Layer w8: U1.15@-1496,-1362.47 -1496,-1406.47 -1470,-1432.47 v2(-1470,-1610.47) -1470,-1791.47 -1433,-1828.47 P1.1@-1433,-1832.47 ; U1.15@-1496,527.53 -1496,483.53 -1470,457.53 v2(-1470,279.53) -1470,98.53 -1433,61.53 P1.1@-1433,57.53 ; U1.15@-511,-1362.24 -511,-1406.24 -485,-1432.24 v2(-485,-1610.24) -485,-1791.24 -448,-1828.24 P1.1@-448,-1832.24 ; U1.15@-511,527.76 -511,483.76 -485,457.76 v2(-485,279.76) -485,98.76 -448,61.76 P1.1@-448,57.76 ; U1.15@474,-1362 474,-1406 500,-1432 v2(500,-1610) 500,-1791 537,-1828 P1.1@537,-1832 ; U1.15@474,528 474,484 500,458 v2(500,280)
  Bottom Layer w8: v2(500,280) 500,99 537,62 P1.1@537,58
MSCK: P1.3 U1.17 | length 3074.1
  Top Layer w8: P1.3@-1624,-1829.47 -1597,-1829.47 -1521,-1753.47 v2@-1521,-1633.47 ; P1.3@-1624,60.53 -1597,60.53 -1521,136.53 v2@-1521,256.53 ; U1.17@-1578,-1422.47 -1539,-1422.47 -1520,-1441.47 v2(-1520,-1633.47) ; U1.17@-1578,467.53 -1539,467.53 -1520,448.53 v2(-1520,256.53) ; P1.3@-639,-1829.24 -612,-1829.24 -536,-1753.24 v2@-536,-1633.24 ; P1.3@-639,60.76 -612,60.76 -536,136.76 v2@-536,256.76 ; U1.17@-593,-1422.24 -554,-1422.24 -535,-1441.24 v2(-535,-1633.24) ; U1.17@-593,467.76 -554,467.76 -535,448.76 v2(-535,256.76) ; P1.3@346,-1829 373,-1829 449,-1753 v2@449,-1633 ; U1.17@392,-1422 431,-1422 450,-1441 v2(450,-1633) ; U1.17@392,468 431,468 450,449 v2(450,257)
  Bottom Layer w8: P1.3@346,61 373,61 449,137 v2@449,257
NetC2_2: C2.2 U2.11 Y1.1 | length 1387.5
  Top Layer w8: Y1.1@-1666,-1209.47 -1644,-1231.47 -1586,-1231.47 -1527,-1172.47 U2.11@-1506,-1172.47 ; Y1.1@-1666,680.53 -1644,658.53 -1586,658.53 -1527,717.53 U2.11@-1506,717.53 ; Y1.1@-681,-1209.24 -659,-1231.24 -601,-1231.24 -542,-1172.24 U2.11@-521,-1172.24 ; Y1.1@-681,680.76 -659,658.76 -601,658.76 -542,717.76 U2.11@-521,717.76 ; Y1.1@304,-1209 326,-1231 384,-1231 443,-1172 U2.11@464,-1172 ; Y1.1@304,681 326,659 384,659 443,718 U2.11@464,718
  Top Layer w12: C2.2@-1723,-1190.47 Y1.1@-1685.31,-1190.47 ; C2.2@-1723,699.53 Y1.1@-1685.31,699.53 ; C2.2@-738,-1190.24 Y1.1@-700.31,-1190.24 ; C2.2@-738,699.76 Y1.1@-700.31,699.76 ; C2.2@247,-1190 Y1.1@284.69,-1190 ; C2.2@247,700 Y1.1@284.69,700
NetC7_1: C7.1 U2.1 | length 479.8
  Top Layer w8: U2.1@-1379.79,-1064.91 C7.1@-1379.79,-984.94 ; U2.1@-1379.79,825.09 C7.1@-1379.79,905.06 ; U2.1@-394.79,-1064.68 C7.1@-394.79,-984.71 ; U2.1@-394.79,825.32 C7.1@-394.79,905.29 ; U2.1@590.21,-1064.44 C7.1@590.21,-984.47 ; U2.1@590.21,825.56 C7.1@590.21,905.53
NetC8_1: C8.1 U2.24 | length 661.6
  Top Layer w8: U2.24@-1351.44,-1093.26 -1321.79,-1093.26 -1286,-1057.47 C8.1@-1256,-1057.47 ; U2.24@-1351.44,796.74 -1321.79,796.74 -1286,832.53 C8.1@-1256,832.53 ; U2.24@-366.44,-1093.02 -336.79,-1093.02 -301,-1057.24 C8.1@-271,-1057.24 ; U2.24@-366.44,796.98 -336.79,796.98 -301,832.76 C8.1@-271,832.76 ; U2.24@618.56,-1092.79 648.21,-1092.79 684,-1057 C8.1@714,-1057 ; U2.24@618.56,797.21 648.21,797.21 684,833 C8.1@714,833
NetC9_1: C9.1 C10.2 L1.1 | length 841.9
  Top Layer w12: C10.2@-1410,-940.79 C9.1@-1410,-884.47 ; C10.2@-1410,949.21 C9.1@-1410,1005.53 ; -1408,-905.47 L1.1@-1324,-905.47 ; -1408,984.53 L1.1@-1324,984.53 ; C10.2@-425,-940.55 C9.1@-425,-884.24 ; C10.2@-425,949.45 C9.1@-425,1005.76 ; -423,-905.24 L1.1@-339,-905.24 ; -423,984.76 L1.1@-339,984.76 ; C10.2@560,-940.32 C9.1@560,-884 ; C10.2@560,949.68 C9.1@560,1006 ; 562,-905 L1.1@646,-905 ; 562,985 L1.1@646,985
